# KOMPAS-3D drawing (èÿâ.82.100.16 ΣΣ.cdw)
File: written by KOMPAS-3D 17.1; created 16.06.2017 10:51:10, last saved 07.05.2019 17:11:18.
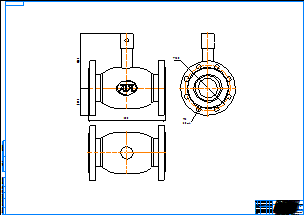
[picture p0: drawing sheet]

Sheet 1: A0, landscape

Title block, sheet 1: name: КШГ.82.100.16 фф; material: Внимание! Данный продукт является объектом авторского права ООО «Торговый Дом АДЛ». / Запрещается изменение, копирование, распространение / (в том числе путем копирования на другие сайты и ресурсы в Интернете) / или любое иное использование информации и объектов без предварительного / согласия правообладателя (ООО «Торговый Дом АДЛ»).; scale: 1:1; sheets: 1; organisation: ООО "Торговый дом АДЛ"; sheet format: A0; stored path: C:\Users\tra\Desktop\2д чертежи\Шаровые краны БИВАЛ\КШ_Бивал_серия_82_85\KOMPAS 2D\КШГ.82.100.16 фф.cdw

Views: Спереди 1, Проекционный вид 2, Проекционный вид 3
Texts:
  Klimkovich
  ADL
Dimensions and other numbers on the sheet: 300; 214,6; 107,5; 180; 18; 8 Отв.; 1:1; 1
